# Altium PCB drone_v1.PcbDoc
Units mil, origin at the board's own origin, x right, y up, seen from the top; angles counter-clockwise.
Board outline 1968.5 x 1417.32 mil, 4 copper layers (Top Layer, GROUND, VCC, Bottom Layer); 89 components, 87 nets, 452 pads, 195 vias.
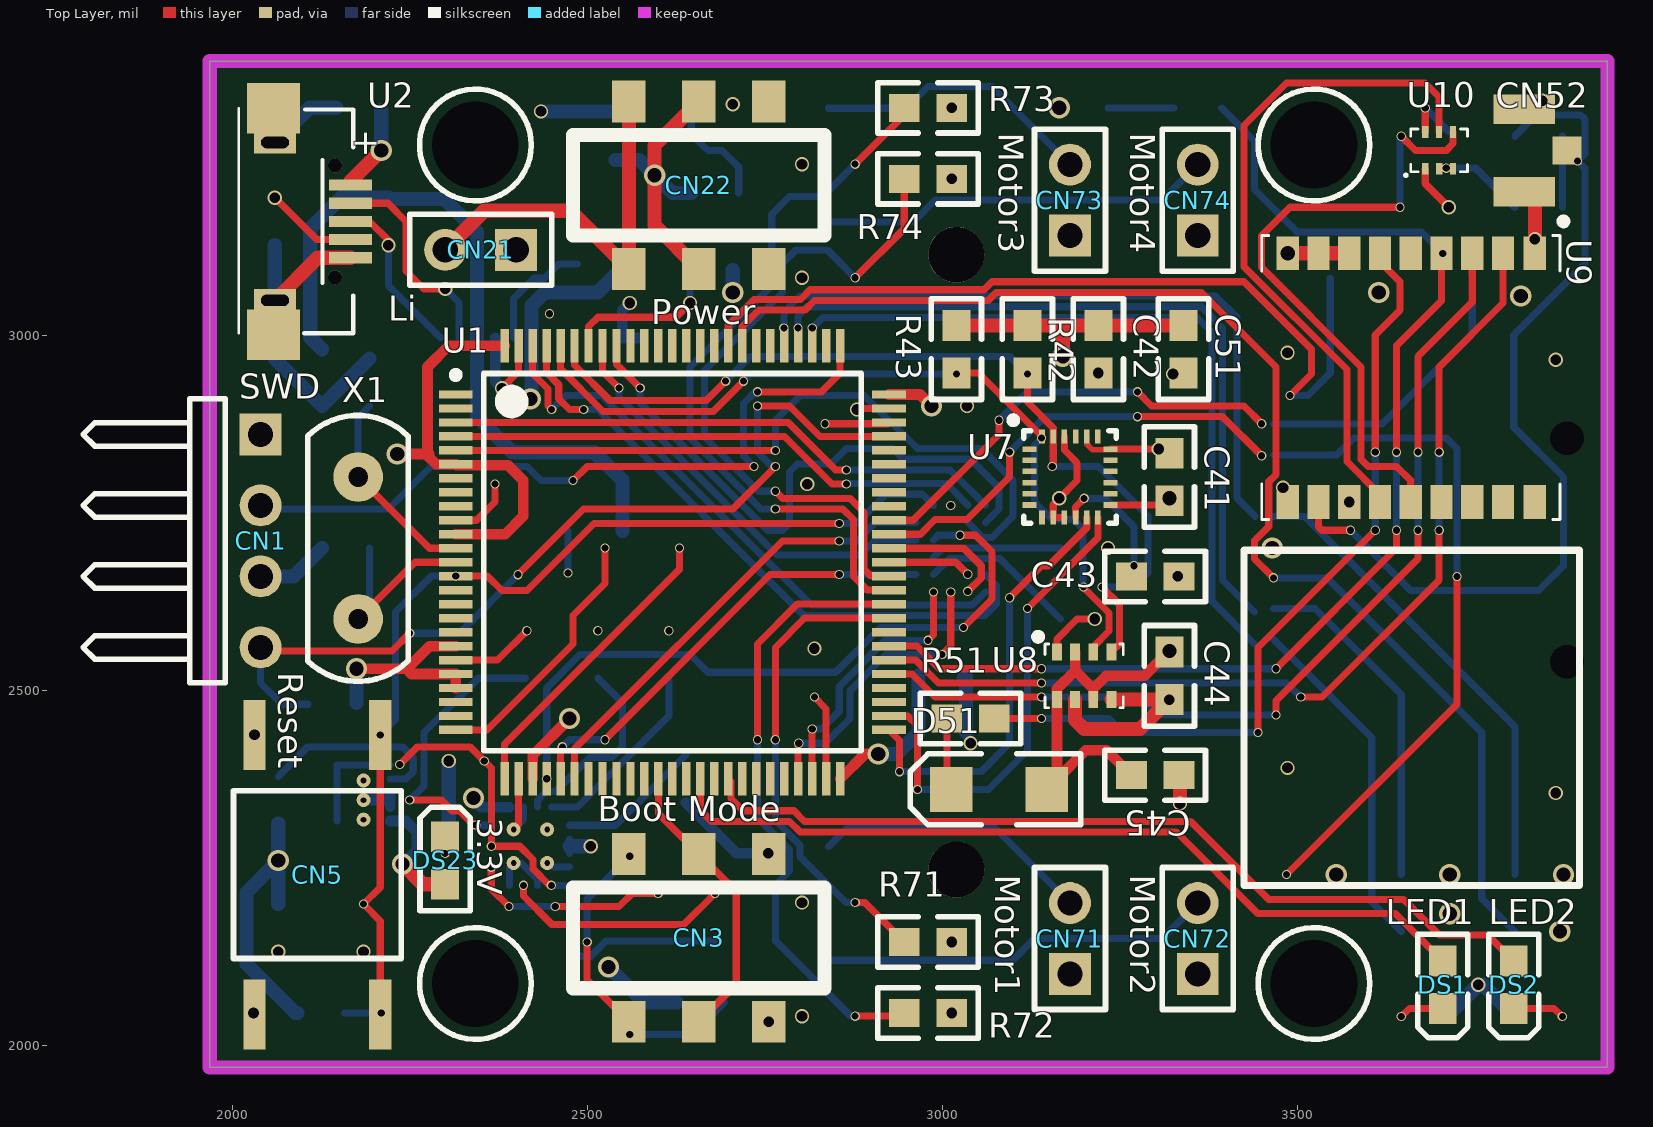
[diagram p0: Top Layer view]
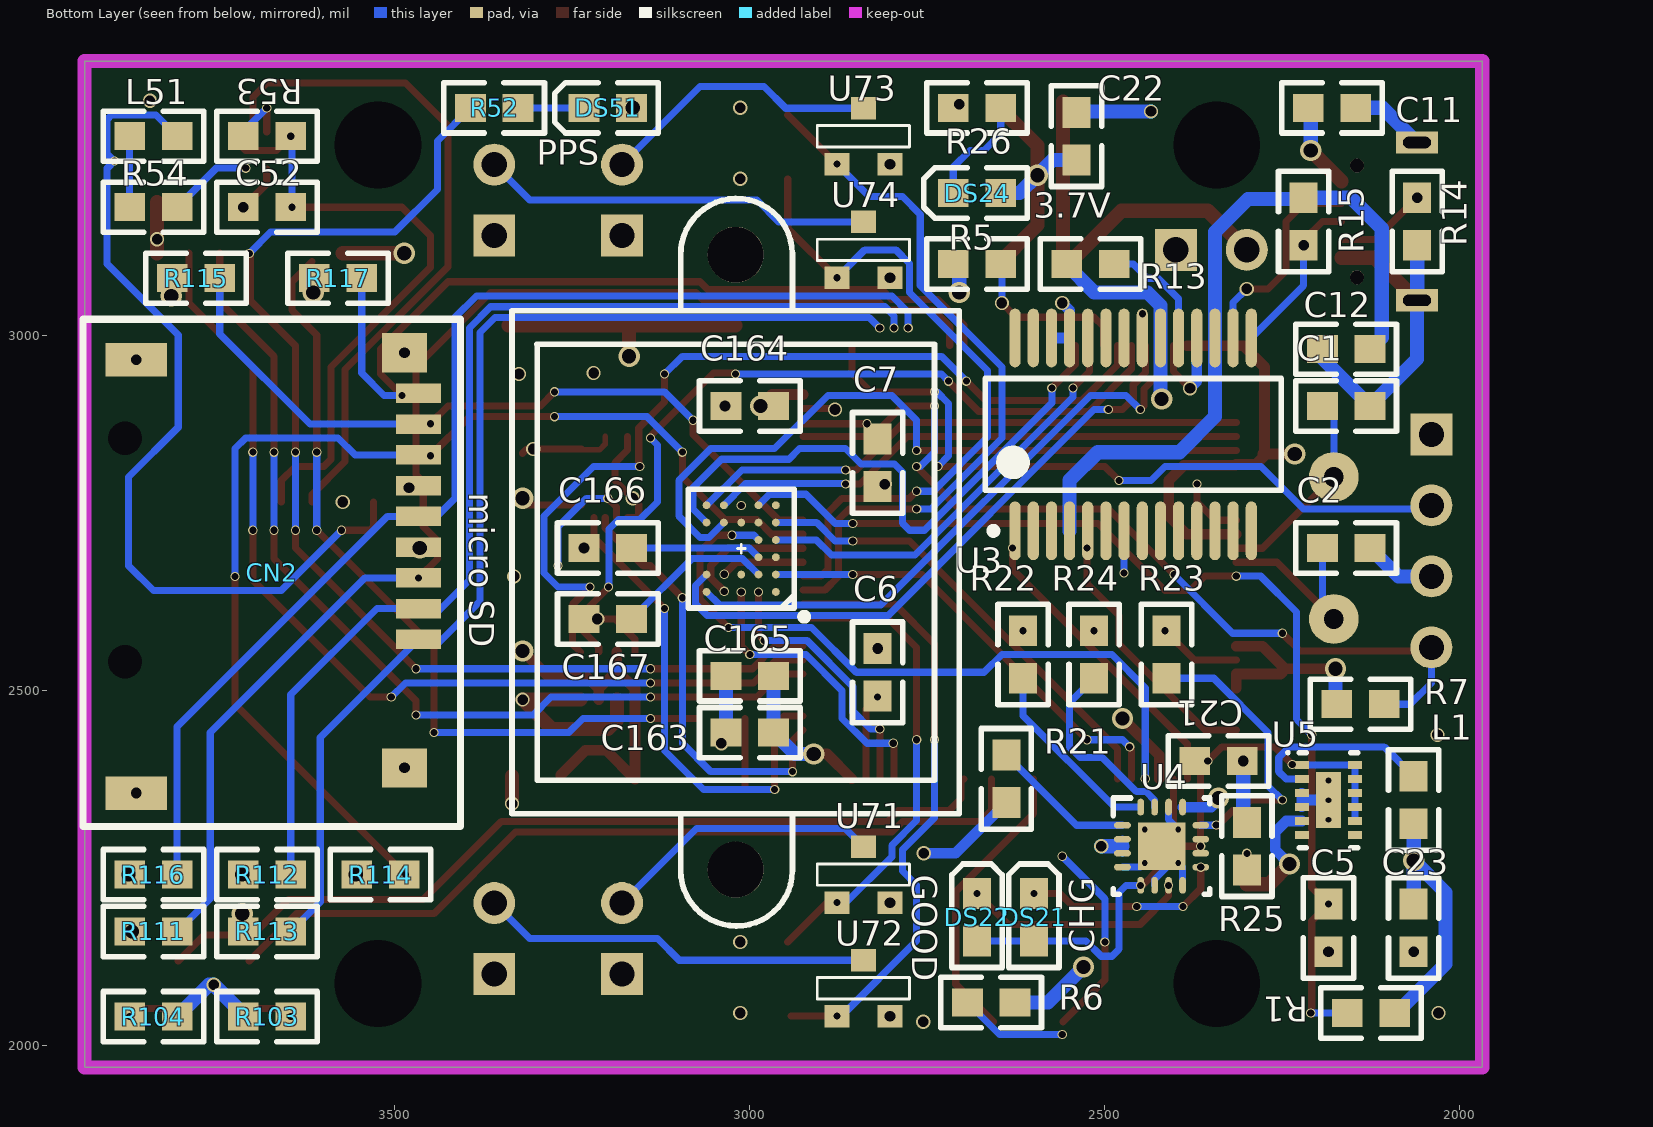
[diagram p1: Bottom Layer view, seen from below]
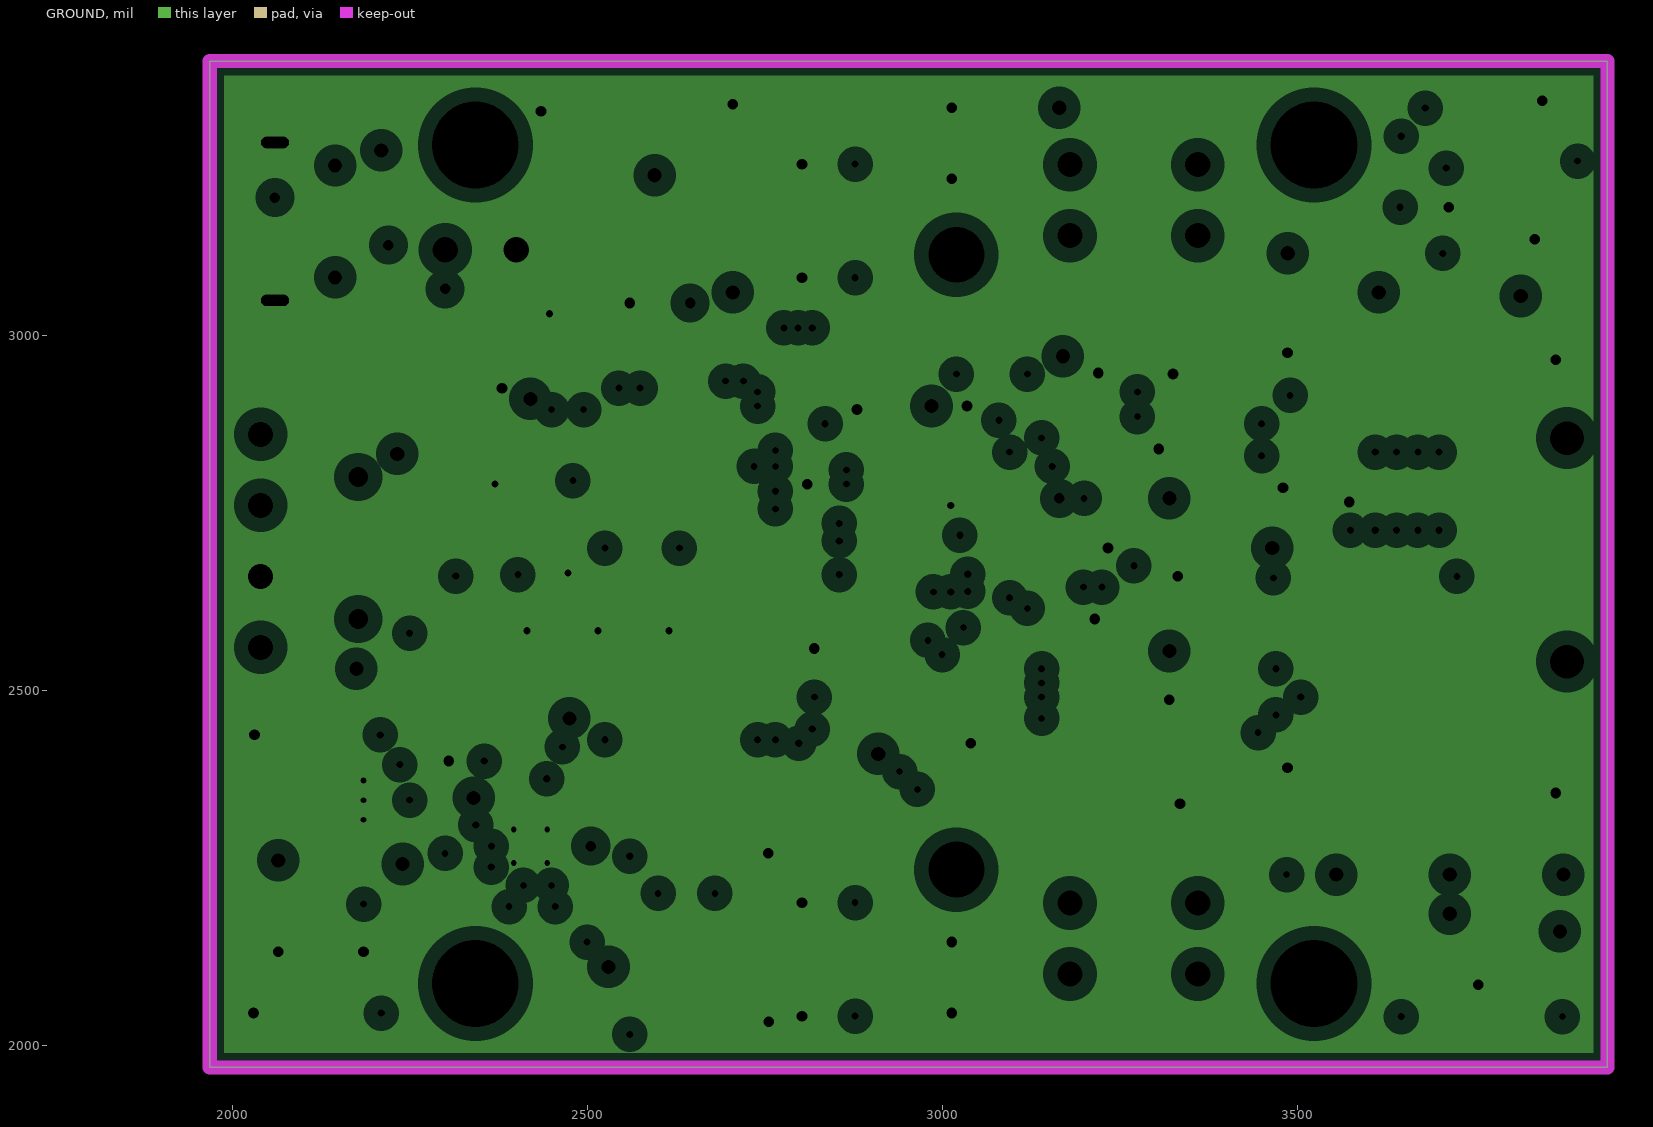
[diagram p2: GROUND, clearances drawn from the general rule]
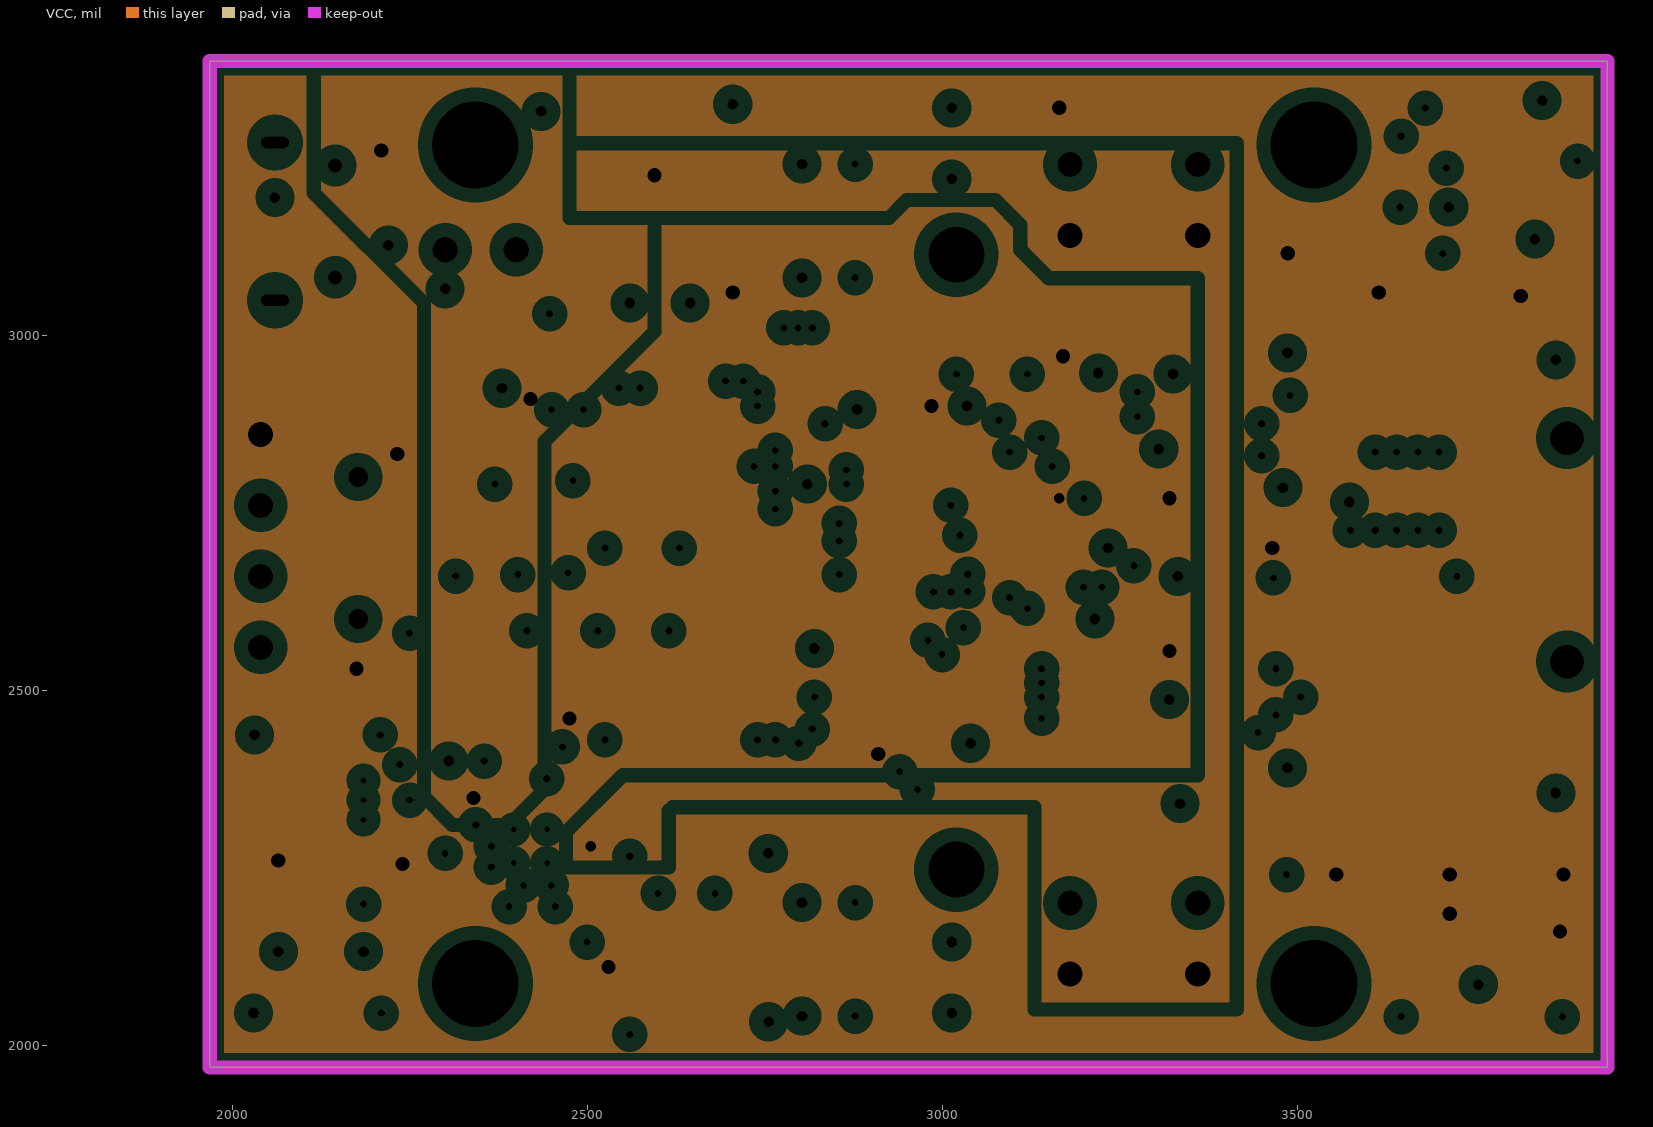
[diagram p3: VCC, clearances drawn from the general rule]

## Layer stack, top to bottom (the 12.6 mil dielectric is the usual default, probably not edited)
Top Layer: signal copper 1.4
Dielectric: core 12.6, FR-4, Dk 4.8
GROUND: plane copper 1.4, net GND
Dielectric: prepreg 12.6, FR-4, Dk 4.8
VCC: plane copper 1.4, net (Multiple Nets)
Dielectric: core 12.6, FR-4, Dk 4.8
Bottom Layer: signal copper 1.4

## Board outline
1968.5,3385.83 3937.01,3385.83 3937.01,1968.5 1968.5,1968.5 1968.5,3385.83

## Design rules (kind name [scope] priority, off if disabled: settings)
Clearance [All] p1: gap=5
ComponentClearance [All] p1: gap=-3937.01 collisioncheckmode=3 verticalgap=10 showdistances=FALSE
PlaneClearance [All] p1: clearance=20
PlaneConnect [All] p1: planeconnectstyle=Relief reliefexpansion=20 reliefentries=4 reliefconductorwidth=10 reliefairgap=10
PolygonConnect [All] p1: connectstyle=Relief reliefconductorwidth=10 reliefentries=4 polygonreliefangle="90 Angle"
RoutingVias [All] p1: holewidth=28 width=50 viastyle="Through Hole" minholewidth=28 minwidth=50 maxholewidth=28 maxwidth=50
SilkscreenOverComponentPads [All] p1: minsilkscreentomaskgap=10
SolderMaskExpansion [All] p1: expansion=4
Width [All] p1: maxlimit=40 minlimit=6 preferedwidth=6
24 further rules are at their usual default settings.

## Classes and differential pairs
component class camera: C163 C164 C165 C166 C167 U13
component class firmware: C11 C12 R13 R14 R15 U2 U3
component class gnss: C51 C52 CN52 D51 DS51 L51 R51 R52 R53 R54 U9 U10
component class mcu: C1 C2 C5 C6 C7 CN1 CN2 CN3 CN5 DS1 DS2 R1 R5 R6 R7 R103 R104 R111 R112 R113 R114 R115 R116 R117 U1 X1
component class motor: CN71 CN72 CN73 CN74 R71 R72 R73 R74 U71 U72 U73 U74
component class power: C21 C22 C23 CN21 CN22 DS21 DS22 DS23 DS24 L1 R21 R22 R23 R24 R25 R26 U4 U5
component class sensor: C41 C42 C43 C44 C45 R42 R43 U7 U8
net class DCMI_D[0..7]: DCMI_D0 DCMI_D1 DCMI_D2 DCMI_D3 DCMI_D4 DCMI_D5 DCMI_D6 DCMI_D7
net class MOTOR_D[0..3]: MOTOR0 MOTOR1 MOTOR2 MOTOR3 MOTOR_D0 MOTOR_D1 MOTOR_D2 MOTOR_D3

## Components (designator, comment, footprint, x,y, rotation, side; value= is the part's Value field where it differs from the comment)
C1 "Cap Semi" C1608-0603 2160,2900 r0 bottom
C2 "Cap Semi" C1608-0603 2160,2700 r0 bottom
C5 "Cap Semi" C1608-0603 2185,2165 r270 bottom
C6 "Cap Semi" C1608-0603 2820,2525 r270 bottom
C7 "Cap Semi" C1608-0603 2820,2820 r90 bottom
C11 "Cap Semi" C1608-0603 2180,3320 r180 bottom
C12 "Cap Semi" C1608-0603 2160,2980 r180 bottom
C21 "Cap Semi" C1608-0603 2340,2400 r0 bottom
C22 "Cap Semi" C1608-0603 2540,3280 r270 bottom
C23 "Cap Semi" C1608-0603 2065,2165 r270 bottom
C41 "Cap Semi" C1608-0603 3320,2800 r90 top
C42 "Cap Semi" C1608-0603 3220,2980 r270 top
C43 "Cap Semi" C1608-0603 3300,2660 r0 top
C44 "Cap Semi" C1608-0603 3320,2520 r90 top
C45 "Cap Semi" C1608-0603 3300,2380 r180 top
C51 "Cap Semi" C1608-0603 3340,2980 r270 top
C52 "Cap Semi" C1608-0603 3680,3180 r0 bottom
C163 "Cap Semi" C1608-0603 3000,2440 r0 bottom
C164 "Cap Semi" C1608-0603 3000,2900 r0 bottom
C165 "Cap Semi" C1608-0603 3000,2520 r0 bottom
C166 "Cap Semi" C1608-0603 3200,2700 r180 bottom
C167 "Cap Semi" C1608-0603 3200,2600 r180 bottom
CN1 "SWD" HDR1X4H 2040,2860 r270 top
CN2 "micro SD" MICRO_SD_PUSH 3880,2660 r270 bottom locked
CN3 "Boot Mode" SWITCH_6 2480,2080 r0 top
CN5 "Reset" Switch6X6 2120,2240 r270 top
CN21 "Li" HDR1X2 2400,3120 r180 top
CN22 "Power" SWITCH_6 2480,3140 r0 top
CN52 "IPEX" IPEX 3820,3260 r0 top
CN71 "Motor1" HDR1X2 3180,2100 r90 top
CN72 "Motor2" HDR1X2 3360,2100 r90 top
CN73 "Motor3" HDR1X2 3180,3140 r90 top
CN74 "Motor4" HDR1X2 3360,3140 r90 top
D51 "IN4148" D1206 3080,2360 r180 top
DS1 "LED1" LED0603_AB 3705,2085 r270 top
DS2 "LED2" LED0603_AB 3805,2085 r270 top
DS21 "CHG" LED0603_AB 2600,2180 r90 bottom
DS22 "GOOD" LED0603_AB 2680,2180 r90 bottom
DS23 "3.3V" LED0603_AB 2300,2260 r90 top
DS24 "3.7V" LED0603_AB 2680,3200 r0 bottom
DS51 "PPS" LED0603_AB 3200,3320 r0 bottom
L1 "Inductor" I1608-0603 2065,2345 r270 bottom
L51 "Inductor" I1608-0603 3840,3280 r0 bottom
R1 "Res Semi" R1608-0603 2125,2045 r0 bottom
R5 "Res Semi" R1608-0603 2680,3100 r180 bottom
R6 "Res Semi" R1608-0603 2660,2060 r0 bottom
R7 "Res Semi" R1608-0603 2140,2480 r180 bottom
R13 "Res Semi" R1608-0603 2520,3100 r180 bottom
R14 "Res Semi" R1608-0603 2060,3160 r270 bottom
R15 "Res Semi" R1608-0603 2220,3160 r270 bottom
R21 "Res Semi" R1608-0603 2638.78,2374.88 r270 bottom
R22 "Res Semi" R1608-0603 2615,2550 r270 bottom
R23 "Res Semi" R1608-0603 2413,2550 r270 bottom
R24 "Res Semi" R1608-0603 2515,2550 r270 bottom
R25 "Res Semi" R1608-0603 2300,2280 r270 bottom
R26 "Res Semi" R1608-0603 2680,3320 r180 bottom
R42 "Res Semi" R1608-0603 3120,2980 r270 top
R43 "Res Semi" R1608-0603 3020,2980 r270 top
R51 "Res Semi" R1608-0603 3040,2460 r180 top
R52 "Res Semi" R1608-0603 3360,3320 r180 bottom
R53 "Res Semi" R1608-0603 3680,3280 r0 bottom
R54 "Res Semi" R1608-0603 3840,3180 r0 bottom
R71 "Res Semi" R1608-0603 2980,2145 r180 top
R72 "Res Semi" R1608-0603 2980,2045 r180 top
R73 "Res Semi" R1608-0603 2980,3320 r180 top
R74 "Res Semi" R1608-0603 2980,3220 r180 top
R103 "Res Semi" R1608-0603 3680,2040 r0 bottom
R104 "Res Semi" R1608-0603 3840,2040 r180 bottom
R111 "Res Semi" R1608-0603 3840,2160 r180 bottom
R112 "Res Semi" R1608-0603 3680,2240 r180 bottom
R113 "Res Semi" R1608-0603 3680,2160 r180 bottom
R114 "Res Semi" R1608-0603 3520,2240 r0 bottom
R115 "Res Semi" R1608-0603 3780,3080 r0 bottom
R116 "Res Semi" R1608-0603 3840,2240 r180 bottom
R117 "Res Semi" R1608-0603 3580,3080 r180 bottom
U1 "STM32F407VGT6" LQFP100_V 2620,2680 r0 top locked
U2 "MICRO-USB" MICRO-USB 2080,3160 r270 top
U3 "IC_FT232RL" SSOP-28 2460,2860 r90 bottom locked
U4 "BQ24232RGTR" RGT0016C 2420,2280 r180 bottom
U5 "TPS62740DSST" DSS0012A 4085,345 r180 bottom
U7 "MPU9250" QFN24_3X3_MPU9250 3180,2800 r0 top locked
U8 "BMP280" LGA8_BMP280 3200,2520 r0 top
U9 "UBLOX_MAX7Q" UBLOX_MAX7Q 3660,2940 r90 top locked
U10 "SI1040X" SI1040X 3700,3260 r0 top
U71 "SOT23_SI2302" SOT23_SI2302 2840,2240 r180 bottom
U72 "SOT23_SI2302" SOT23_SI2302 2840,2080 r180 bottom
U73 "SOT23_SI2302" SOT23_SI2302 2840,3280 r180 bottom
U74 "SOT23_SI2302" SOT23_SI2302 2840,3120 r180 bottom
X1 "8MHz" XTAL-0.2 2020,2680 r90 top

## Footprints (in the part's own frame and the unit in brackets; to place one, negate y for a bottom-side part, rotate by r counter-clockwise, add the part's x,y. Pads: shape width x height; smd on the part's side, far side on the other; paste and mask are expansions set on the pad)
C1608-0603 [mm]
  rect 1.1x1 smd: 1(-0.85,0) 2(0.85,0)
  silkscreen extent -1.8,-0.9 1.8,0.9
D1206 [mm]
  rect 1.52x1.6 smd: 1(-1.71,0) 2(1.71,0)
  silkscreen extent -2.92,-1.27 3.17,1.27
DSS0012A [mm]
  rect 0.5x0.28 smd paste-0.14 mask+0.076: 1(47.31,52.05) 2(47.31,51.55) 3(47.31,51.05) 4(47.31,50.55) 5(47.31,50.05) 6(47.31,49.55) 7(49.21,49.55) 8(49.21,50.05) 9(49.21,50.55) 10(49.21,51.05) 11(49.21,51.55) 12(49.21,52.05)
  round 0.5 / inner round 1.524 / far side round 0.5 hole 0.2 mask+0.051: 13(48.26,50.8) 13(48.26,50.1) 13(48.26,51.5)
  rect 0.9x2 smd paste-0.45 mask+0.076: 13(48.26,50.8)
  silkscreen extent 46.76,49.1 49.31,52.55
HDR1X2 [mm] "Connector; Header; 2 Position"
  rect 1.5x1.5 hole 0.9: 1(0,0)
  round 1.5 hole 0.9: 2(2.54,0)
  silkscreen extent -1.27,-1.27 3.81,1.27
HDR1X4H [mm] "Connector; Header; 4 Position; Right Angle"
  rect 1.5x1.5 hole 0.9: 1(0,0)
  round 1.5 hole 0.9: 2(2.54,0) 3(5.08,0) 4(7.62,0)
  silkscreen extent -1.27,-6.35 8.89,-1.27
I1608-0603 [mm]
  rect 1.1x1 smd: 1(-0.85,0) 2(0.85,0)
  silkscreen extent -1.8,-0.9 1.8,0.9
IPEX [mm]
  rect 2.2x1.05 smd paste+0 mask+0.05: 1(0,1.475) 2(0,-1.475)
  rect 1.05x1 smd paste+0 mask+0.05: 3(1.525,0)
LED0603_AB [mm]
  rect 1.1x1 smd: 1(-0.85,0) 2(0.85,0)
  silkscreen extent -1.8,-0.9 1.91,0.9
LGA8_BMP280 [mm]
  rect 0.35x0.6 smd paste+0 mask+0.03: 1(-0.975,0.85) 2(-0.325,0.85) 3(0.325,0.85) 4(0.975,0.85) 5(0.975,-0.85) 6(0.325,-0.85) 7(-0.325,-0.85) 8(-0.975,-0.85)
  silkscreen extent -1.77,-1.14 1.4,1.52
LQFP100_V [mm] "Thin QFP, 100-Leads, Body 14x14mm, Pitch 0.5mm, ST Recommended"
  rect 1.2x0.3 smd: 1(-7.75,6) 2(-7.75,5.5) 3(-7.75,5) 4(-7.75,4.5) 5(-7.75,4) 6(-7.75,3.5) 7(-7.75,3) 8(-7.75,2.5) 9(-7.75,2) 10(-7.75,1.5) 11(-7.75,1) 12(-7.75,0.5) 13(-7.75,0) 14(-7.75,-0.5) 15(-7.75,-1) 16(-7.75,-1.5) 17(-7.75,-2) 18(-7.75,-2.5) 19(-7.75,-3) 20(-7.75,-3.5) 21(-7.75,-4) 22(-7.75,-4.5) 23(-7.75,-5) 24(-7.75,-5.5) 25(-7.75,-6) 51(7.75,-6) 52(7.75,-5.5) 53(7.75,-5) 54(7.75,-4.5) 55(7.75,-4) 56(7.75,-3.5) 57(7.75,-3) 58(7.75,-2.5) 59(7.75,-2) 60(7.75,-1.5) 61(7.75,-1) 62(7.75,-0.5) 63(7.75,0) 64(7.75,0.5) 65(7.75,1) 66(7.75,1.5) 67(7.75,2) 68(7.75,2.5) 69(7.75,3) 70(7.75,3.5) 71(7.75,4) 72(7.75,4.5) 73(7.75,5) 74(7.75,5.5) 75(7.75,6)
  rect 0.3x1.2 smd: 26(-6,-7.75) 27(-5.5,-7.75) 28(-5,-7.75) 29(-4.5,-7.75) 30(-4,-7.75) 31(-3.5,-7.75) 32(-3,-7.75) 33(-2.5,-7.75) 34(-2,-7.75) 35(-1.5,-7.75) 36(-1,-7.75) 37(-0.5,-7.75) 38(0,-7.75) 39(0.5,-7.75) 40(1,-7.75) 41(1.5,-7.75) 42(2,-7.75) 43(2.5,-7.75) 44(3,-7.75) 45(3.5,-7.75) 46(4,-7.75) 47(4.5,-7.75) 48(5,-7.75) 49(5.5,-7.75) 50(6,-7.75) 76(6,7.75) 77(5.5,7.75) 78(5,7.75) 79(4.5,7.75) 80(4,7.75) 81(3.5,7.75) 82(3,7.75) 83(2.5,7.75) 84(2,7.75) 85(1.5,7.75) 86(1,7.75) 87(0.5,7.75) 88(0,7.75) 89(-0.5,7.75) 90(-1,7.75) 91(-1.5,7.75) 92(-2,7.75) 93(-2.5,7.75) 94(-3,7.75) 95(-3.5,7.75) 96(-4,7.75) 97(-4.5,7.75) 98(-5,7.75) 99(-5.5,7.75) 100(-6,7.75)
  silkscreen extent -7.87,-6.75 6.75,6.82, body extent -7,-7 7,7, height 1.6
MICRO-USB [mm]
  rect 0.4x1.55 smd: 1(-1.3,2.2) 2(-0.65,2.2) 3(0,2.2) 4(0.65,2.2) 5(1.3,2.2)
  rect 1.8x1.9 smd: 6(-4.05,-0.55) 6(4.05,-0.55)
  rect 0.8x1.5 hole 0.4 slot 1 at 90 deg: 6(-2.825,-0.5) 6(2.825,-0.5)
  round 0.5 hole 0.5 unplated: ""(-2,1.65) ""(2,1.65)
  silkscreen extent -4.05,-1.8 4,2.3
MICRO_SD_PUSH [mm]
  rect 0.7x1.6 smd: 1(2.25,10.5) 2(1.15,10.5) 3(0.05,10.5) 4(-1.05,10.5) 5(-2.15,10.5) 6(-3.25,10.5) 7(-4.35,10.5) 8(-5.45,10.5) 9(-6.55,10.5)
  rect 1.4x1.6 smd: 10(-8,10) 10(6.85,10)
  rect 1.2x2.2 smd: 10(-7.75,0.4) 10(7.75,0.4)
  round 1 hole 1.2: ""(-4.95,0) ""(3.05,0)
  silkscreen extent -9.2,-1.5 8.95,12
QFN24_3X3_MPU9250 [mm]
  rect 0.5x0.2 smd paste+0 mask+0.03: 1(-1.45,1) 2(-1.45,0.6) 3(-1.45,0.2) 4(-1.45,-0.2) 5(-1.45,-0.6) 6(-1.45,-1) 13(1.45,-1) 14(1.45,-0.6) 15(1.45,-0.2) 16(1.45,0.2) 17(1.45,0.6) 18(1.45,1)
  rect 0.2x0.5 smd paste+0 mask+0.03: 7(-1,-1.45) 8(-0.6,-1.45) 9(-0.2,-1.45) 10(0.2,-1.45) 11(0.6,-1.45) 12(1,-1.45) 19(1,1.45) 20(0.6,1.45) 21(0.2,1.45) 22(-0.2,1.45) 23(-0.6,1.45) 24(-1,1.45)
  silkscreen extent -2.15,-1.65 1.65,2.16
R1608-0603 [mm]
  rect 1.1x1 smd: 1(-0.85,0) 2(0.85,0)
  silkscreen extent -1.8,-0.9 1.8,0.9
RGT0016C [mm]
  oval 0.6x0.24 smd paste-0.102 mask+0.051: 1(-1.4,0.75) 2(-1.4,0.25) 3(-1.4,-0.25) 4(-1.4,-0.75) 9(1.4,-0.75) 10(1.4,-0.25) 11(1.4,0.25) 12(1.4,0.75)
  oval 0.24x0.6 smd paste-0.102 mask+0.051: 5(-0.75,-1.4) 6(-0.25,-1.4) 7(0.25,-1.4) 8(0.75,-1.4) 13(0.75,1.4) 14(0.25,1.4) 15(-0.25,1.4) 16(-0.75,1.4)
  round 0.5 / inner round 1.524 / far side round 0.5 hole 0.203 mask+0.051: 17(-0.6,-0.6) 17(-0.6,0.6) 17(0.6,-0.6) 17(0.6,0.6)
  rect 1.7x1.7 smd paste-0.837 mask+0.051: 17(0,0)
  silkscreen extent -1.72,-1.73 1.72,1.73
SI1040X [mm]
  rect 0.22x0.42 smd paste+0 mask+0.05: 1(-0.5,-0.66) 2(0,-0.66) 3(0.5,-0.66) 4(0.5,0.66) 5(-0.008,0.66) 6(-0.5,0.66)
  silkscreen extent -1.24,-0.94 1.02,0.76
SOT23_SI2302 [mm]
  rect 0.9x0.8 smd: 1(-0.95,-1) 2(0.95,-1) 3(0,1)
  silkscreen extent -1.65,-0.38 1.65,0.38
SSOP-28 [mm] "28-Pin SSOP 0.65 mm Pitch"
  oval 2.1x0.4 smd: 1(-3.45,4.225) 2(-3.45,3.575) 3(-3.45,2.925) 4(-3.45,2.275) 5(-3.45,1.625) 6(-3.45,0.975) 7(-3.45,0.325) 8(-3.45,-0.325) 9(-3.45,-0.975) 10(-3.45,-1.625) 11(-3.45,-2.275) 12(-3.45,-2.925) 13(-3.45,-3.575) 14(-3.45,-4.225) 15(3.45,-4.225) 16(3.45,-3.575) 17(3.45,-2.925) 18(3.45,-2.275) 19(3.45,-1.625) 20(3.45,-0.975) 21(3.45,-0.325) 22(3.45,0.325) 23(3.45,0.975) 24(3.45,1.625) 25(3.45,2.275) 26(3.45,2.925) 27(3.45,3.575) 28(3.45,4.225)
  silkscreen extent -3.57,-5.3 2,5.3, body extent -2.7,-5.3 2.7,5.3, height 2
Switch6X6 [mm]
  rect 2.5x0.8 smd: 1(-5,2.25) 2(5,2.25) 3(-5,-2.25) 4(5,-2.25)
  silkscreen extent -3,-3 3,3
SWITCH_6 [mm]
  rect 1.2x1.5 smd: 1(2,4.8) 2(4.5,4.8) 3(7,4.8) 4(2,-1.2) 5(4.5,-1.2) 6(7,-1.2)
  silkscreen extent 0,0 9,3.6
UBLOX_MAX7Q [mm]
  rect 1.2x0.8 smd paste+0 mask+0.05: 1(4.45,-4.44) 2(4.45,-3.3) 3(4.45,-2.2) 4(4.45,-1.1) 5(4.45,0) 6(4.45,1.1) 7(4.45,2.2) 8(4.45,3.3) 9(4.45,4.4) 10(-4.45,4.4) 11(-4.45,3.3) 12(-4.45,2.2) 13(-4.45,1.1) 14(-4.45,0) 15(-4.45,-1.1) 16(-4.45,-2.2) 17(-4.45,-3.3) 18(-4.45,-4.44)
  silkscreen extent -5.08,-5.59 5.71,5.33
XTAL-0.2 [mil]
  round 70 hole 28: 1(-79.92,-157.48) 2(120.08,-157.48)
  silkscreen extent -168,-228 207,-86

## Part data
C1 C2 C5 C6 C7 C11 C12 C21 C22 C23 C41 C42 C43 C44 C45 C51 C52 C163 C164 C165 C166 C167: "Capacitor (Semiconductor SIM Model)"
CN1: library part "Header 4H", "Header, 4-Pin, Right Angle"
CN2: library part MICRO_SD_PUSH
CN3 CN22: library part SWITCH_6
CN5: library part Switch6X6, "Switch"
CN21 CN71 CN72 CN73 CN74: library part "Header 2", "Header, 2-Pin"
D51: library part Diode, "Default Diode"
DS1 DS2 DS21 DS22 DS23 DS24 DS51: library part LED3, "Typical BLUE SiC LED"
R1 R5 R6 R7 R13 R14 R15 R21 R22 R23 R24 R25 R26 R42 R43 R51 R52 R53 R54 R71 R72 R73 R74 R103 R104 R111 R112 R113 R114 R115 R116 R117: "Semiconductor Resistor"
U3: "FT232R USB UART"
U4 U5: "Imported"
U7: library part QFN24_3X3_MPU9250
U8: library part LGA8_BMP280
X1: library part XTAL, "Crystal Oscillator"

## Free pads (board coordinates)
  round 118.11 hole 122.05: 0(2342.52,2086.61) 0(2342.52,3267.72) 0(3523.62,2086.61) 0(3523.62,3267.72)
  round 78.74 hole 78.74: 1(3020,3113.07) 2(3020,2246.93)
  round 11.02 smd far side: A1(2963.31,2638.2) A2(2987.72,2638.2) A3(3012.13,2638.2) A4(3036.54,2638.2) A5(3060.95,2638.2) B1(2963.31,2662.61) B2(2987.72,2662.61) B3(3012.13,2662.61) B4(3036.54,2662.61) B5(3060.95,2662.61) C1(2963.31,2687.02) C2(2987.72,2687.02) D1(2963.31,2711.43) D2(2987.72,2711.43) E1(2963.31,2735.83) E2(2987.72,2735.83) E3(3012.13,2735.83) E4(3036.54,2735.83) E5(3060.95,2735.83) F1(2963.31,2760.24) F2(2987.72,2760.24) F3(3012.13,2760.24) F4(3036.54,2760.24) F5(3060.95,2760.24)

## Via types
v1: diameter 13, hole 10, Top Layer to Bottom Layer, 121 vias
v2: diameter 20, hole 15, Top Layer to Bottom Layer, 48 vias
v3: diameter 30, hole 20, Top Layer to Bottom Layer, 26 vias

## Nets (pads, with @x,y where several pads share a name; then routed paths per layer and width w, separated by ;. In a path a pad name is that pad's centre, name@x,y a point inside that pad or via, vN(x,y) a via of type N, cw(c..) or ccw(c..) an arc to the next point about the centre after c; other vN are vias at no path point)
3.3V: C23.1 C41.1 C42.1 C44.2 C45.2 C51.1 C163.1 C164.1 C165.1 CN1.1 CN2.4 D51.1 DS23.1 DS51.1 L1.2 R1.1 R5.1 R6.1 R7.1 R42.1 R43.1 R111.1 R112.1 R113.1 R114.2 R115.2 R116.1 R117.1 U1.6 U1.11 U1.19 U1.21 U1.22 U1.28 U1.50 U1.75 U1.100 U5.5 U7.8 U7.9 U7.13 U7.22 U8.2 U8.6 U8.8 U9.7 U9.8 U9.9 | length 3164.2
  Top Layer w10: U7.9 U7.8 3156.38,2761.38 v2(3165,2770) 3190,2795 3190,2820 3172.13,2837.87 U7.22 ; U7.13 C41.1@3314.09,2760.63
  Top Layer w15: v3(2175,2530) 2245,2530 2252.48,2522.52 U1.21 U1.22 ; v3(2232.5,2832.5) 2277.5,2832.5 2275,2830 ; 2246.22,2530 2278.11,2561.89 U1.19 ; U1.11 2384.37,2719.37 2410,2745 2410,2795 2388.48,2816.52 2316.16,2816.52 U1.6 2287.2,2817.8 2275,2830 ; U1.100 2305.12,2985.12 2275,2955 2275,2830 ; U1.28 2423.15,2408.15 v3(2475,2460) ; U1.50 2891.34,2410 v3(2910,2410) ; U1.75 2968.78,2916.22 v3(2985,2900) ; U8.2 3187.2,2527.2 ; U8.6 3212.8,2501.61 ; C45.2 3231.54,2415 3202.32,2415 3161.61,2374.29 U8.8 3161.61,2501.61 3187.2,2527.2 ; v3(3320,2555) 3285,2520 3231.18,2520 3212.8,2501.61 ; 3187.2,2527.2 3212.8,2501.61
  Top Layer w20: v3(2240,2255) 2268.46,2226.54 DS23.1 ; R43.1 R42.1 3170,3013.46 ; v3(3170,2970) 3170,3013.46 ; C51.1 C42.1 3170,3013.46 ; v3(3486.77,3115.2) U9.8 U9.7
  Bottom Layer w15: U5.5 2244.53,2315.47 2260,2300 2260,2275 v3(2240,2255)
  Bottom Layer w20: C23.1 v3(2065,2260) ; L1.2 v3(2065,2260) ; R1.1 2088.98,2045 2020,2113.98 2020,2215 v3(2065,2260) ; R7.1@2175,2481.54 v3(2175,2530) ; v3(2530,2110) 2580,2060 R6.1 ; v3(2705,3060) R5.1@2705,3091.54 ; v3(2910,2410) 2936.54,2410 C163.1 C165.1
  other v3: 3870,2160 3715,2185 3555,2240 3715,2240 3875,2240 3465,2700 3320,2770 3815,3055 3615,3060 3165,3320
3.3V_FT232: C12.2 R15.1 U3.4 U3.17 | length 1020.3
  Bottom Layer w20: C12.2 2110,2996.54 2110,3150 2153.46,3193.46 R15.1 ; R15.1@2221.77,3191.69 2298.31,3191.69 2344.84,3145.16 U3.17 2344.84,2885.16 2395,2835 2510,2835 2549.57,2795.43 U3.4
3.7V_LI: C22.2 CN22.2 CN22.5 CN71.1 CN72.1 CN73.1 CN74.1 DS24.1 U4.2 U4.3 | length 463.1
  Top Layer w20: CN22.5 2595,3154.92 v3(2595,3225) 2595,3266.81 CN22.2
  Bottom Layer w10: U4.3 2475.12,2280 U4.2
  Bottom Layer w20: 2475.12,2280 v2(2505,2280) ; C22.2 2573.46,3246.54 v3(2595,3225) 2620,3200 DS24.1
4.4V_BQOUT: C21.2 DS21.1 DS22.1 U4.5 U4.10 U4.11 U5.1 U5.8 U5.9 U5.10 U5.11 U5.12 | length 857.9
  Top Layer w10: v1(2236,2395) 2261,2420 2335,2420 v1(2355,2400) 2365,2390 v1(2365,2280) 2405,2280 2423.78,2261.22 2423.78,2248.16 2447.06,2224.88 v1(2449.53,2224.88)
  Bottom Layer w10: U5.8 U5.9 U5.10 U5.11 U5.12 2147.76,2394.37 U5.1@2222.24,2394.37 ; v1(2449.53,2224.88) 2470.12,2224.88 2480,2215 2480,2135 2490,2125 2505,2125 2526.54,2146.54 DS21.1 DS22.1
5V_USB: C11.1 R13.1 U2.1 U3.20 U4.13 | length 461
  Top Layer w20: U2.1@2166.61,3216.61 v3(2210,3260)
  Bottom Layer w15: v3@2340,2345 2349.88,2335.12 U4.13@2390.43,2335.12
  Bottom Layer w20: v3(2210,3260) C11.1@2210,3316.54 ; v3@2421.61,2910 2421.61,2985.83 2421.61,3041.61 2440,3060 2515,3060 2553.46,3098.46 R13.1
  other v3: 2340,2348 2420,2910
BOOT1: CN3.2 CN3.5 U1.37 | length 409.4
  Top Layer w10: U1.37 2600.32,2325.83 CN3.2 2710,2216.14 2710,2085.59 CN3.5
DCMI_D0: pad.B4 U1.63 | length 117.9
  Top Layer w10: U1.63 3019,2680 v1(3036,2663)
DCMI_D1: pad.A4 U1.64 | length 184
  Top Layer w10: U1.64 3030.32,2699.68 3055,2675 3055,2658 v1(3036,2639)
DCMI_D2: pad.B5 U1.97 | length 879.4
  Top Layer w10: U1.97 2442.83,2947.17 2460,2930 2460,2910 2475,2895 v1(2495,2895)
  Bottom Layer w10: v1(2495,2895) 2515,2895 2805,2605 3060,2605 3076.46,2621.46 3076.46,2647.09 pad.B5
DCMI_D3: pad.A5 U1.98 | length 850.2
  Top Layer w10: U1.98 2423.15,2945.64 2445,2923.79 2445,2900 v1(2450,2895)
  Bottom Layer w10: v1(2450,2895) 2470,2915 2520,2915 2815,2620 3042.75,2620 pad.A5
DCMI_D4: pad.F5 U1.3 | length 794.4
  Top Layer w10: U1.3 2783.15,2876.85 2850,2810 v1(2865,2810)
  Bottom Layer w10: v1(2865,2810) 3011.19,2810 pad.F5
DCMI_D5: pad.E5 U1.92 | length 844
  Top Layer w10: U1.92 2541.26,2958.74 v1(2574.65,2925.35)
  Bottom Layer w10: v1(2574.65,2925.35) 2574.65,2904.14 2753.79,2725 2775,2725 2785,2735 2785,2807.02 2796.17,2818.19 2843.19,2818.19 2865,2840 2930,2840 2945,2825 3040,2825 3080,2785 3080,2754.89 pad.E5
DCMI_D6: pad.F4 U1.4 | length 762.1
  Top Layer w10: U1.4 2777.83,2857.17 2845,2790 v1(2865,2790)
  Bottom Layer w10: v1@2865,2790.76 3006.02,2790.76 pad.F4
DCMI_D7: pad.E4 U1.5 | length 1026.4
  Top Layer w10: U1.5 v1(2765,2837.48)
  Bottom Layer w10: v1(2765,2837.48) 2765,2880 2800,2915 2890,2915 2965,2840 3055,2840 3100,2795 3100,2745 3070,2715 3057.37,2715 pad.E4
GND: C1.1 C2.1 C5.2 C6.1 C7.1 C11.2 C12.1 C21.1 C22.1 C23.2 C41.2 C42.2 C43.2 C44.1 C45.1 C51.2 C52.2 C163.2 C164.2 C165.2 C166.1 C167.1 CN1.3 CN2.6 CN2.10 CN3.3 CN3.6 CN5.3 CN5.4 CN21.1 CN52.1 CN52.2 pad.F3 R14.2 R21.2 R22.1 R23.1 R24.1 R25.1 R26.1 R71.1 R72.1 R73.1 R74.1 R103.2 R104.2 U1.10 U1.20 U1.27 U1.74 U1.99 U2.5 U2.6 U3.7 U3.18 U3.21 U3.25 U3.26 U4.4 U4.6 U4.8 U4.14 U4.17 U5.3 U5.4 U5.13 U7.18 U7.20 U8.1 U8.5 U8.7 U9.1 U9.10 U9.12 U10.1 U71.2 U72.2 U73.2 U74.2 | length 2706.5
  Top Layer w8: U7.20 3203.62,2846.33 3211.71,2838.24 3235.96,2838.24 U7.18
  Top Layer w10: U1.20 2373.74,2542.2 v1(2415,2583.46) ; U1.10 2344.06,2739.06 2370,2765 v1(2370,2790) ; v2(2380,2925) 2403.46,2948.46 U1.99 ; U4.17@2396.38,2303.62 2403.46,2310.71 U1.27 ; v2@2881.54,2896.54 U1.74 ; U8.1 3161.61,2571.61 3190,2600 v2(3215,2600) ; U7.18 3314.09,2839.37 C41.2 ; U10.1 3680.32,3213.15 v2(3713.46,3180)
  Top Layer w20: U2.6@2060.32,3048.78 2120.36,3108.82 U2.5 ; U8.7 3187.2,2457.8 3200,2445 3278.46,2445 v2(3320,2486.54) U8.5 ; v2(3335,2340) C45.1@3335,2378.46 ; U9.1 CN52.2@3834.8,3187.13
  Bottom Layer w10: U4.8 2390.47,2250.47 U4.17@2396.38,2256.38 ; U4.17@2396.38,2303.62 2410.16,2317.4 U4.14 ; U4.17@2406.57,2256.38 2429.84,2233.11 U4.6 ; U4.17@2443.62,2256.38 2449.53,2250.47 U4.4 ; v1@2472.8,2667.8 U3.7
  Bottom Layer w15: U5.13@2185,2345 2222.4,2345 ; U5.4@2222.4,2335.47 2222.4,2345 ; U5.3 2222.4,2345 ; U3.18 2370.43,2934.57 v2(2380,2925) ; v2(2560,3045) 2549.57,3034.57 U3.25 U3.26 ; R21.2 2710.2,2270 v2(2755,2270)
  Bottom Layer w20: CN1.3 2086.54,2660 C2.1 ; U2.6@2060,3049.09 R14.2 ; U2.6@2060.32,3048.78 2060.32,2966.22 C1.1 C12.1@2193.46,2966.93 ; U2.6@2060.32,3271.22 2109.09,3320 C11.2 ; R25.1@2305,2318.46 v2(2305,2400) ; v2(2435,3315) C22.1@2538.46,3315 ; C165.2@3030,2516.54 C165.2 C163.2 ; R103.2 3713.46,2043.46 v2(3755,2085) 3761.54,2085 R104.2
  other v1: 2515,2583.46 2615,2583.46 2473,2665 3012,2760 2447,3030
  other v2: 2755.59,2032.76 2802.6,2040.63 2030,2045 3013.46,2045 2065,2131.54 2185,2131.54 3013.46,2145 2802.6,2200.63 3864.25,2354.88 3486.3,2390.32 3040,2425 2031.42,2436.85 2820,2558.46 3332,2660 3233.46,2700 3573.39,2764.8 3480,2785 2810,2790 3305,2839.37 2880,2895 3035,2900 3325,2945 3220,2946.54 3864.25,2965.12 3486.3,2974.96 2802.6,3080.63 3834.8,3135 3013.46,3220 2802.6,3240.63 3013.46,3320 2705,3325 3845,3330
MOTOR_D0: R71.2 U1.59 U71.1 | length 682.9
  Top Layer w10: v1(2765,2430) 2765,2560 2806.26,2601.26 U1.59 ; v1(2877.4,2200.63) 2890.91,2200.63 R71.2
  Bottom Layer w10: v1(2765,2430) 2765,2316.21 2800,2281.21 2800,2265 2864.37,2200.63 v1(2877.4,2200.63)
MOTOR_D1: R72.2 U1.60 U72.1 | length 868.3
  Top Layer w10: v1(2740,2430) 2740,2565 2795.94,2620.94 U1.60 ; v1(2877.4,2040.63) R72.2@2942.17,2040.63
  Bottom Layer w10: v1(2740,2430) 2740,2320 2785,2275 2785,2245 2765,2225 2765,2146.76 U72.1@2871.13,2040.63
MOTOR_D2: R73.2 U1.61 U73.1 | length 1022.8
  Top Layer w10: v1(2765,2755) 2860,2755 2875,2740 2875,2660 2894.37,2640.63 U1.61 ; v1(2877.4,3240.63) R73.2@2946.54,3309.76
  Bottom Layer w10: v1(2765,2755) 2745,2755 2645,2855 2645,2955 2759.88,3069.88 2759.88,3169.88 2785,3195 2831.77,3195 v1(2877.4,3240.63)
MOTOR_D3: R74.2 U1.62 U74.1 | length 972.8
  Top Layer w10: v1(2765,2780) 2775,2770 2870,2770 2890,2750 2890,2670 2899.68,2660.32 U1.62 ; v1(2877.4,3080.63) 2946.54,3149.76 R74.2
  Bottom Layer w10: v1(2765,2780) 2741.21,2780 2665,2856.21 2665,2950 2774.88,3059.88 2774.88,3100.52 2794.36,3120 2838.03,3120 v1(2877.4,3080.63)
NetC1_2: C1.2 U1.12 X1.2 | length 285.5
  Top Layer w10: X1.2 2277.87,2699.68 U1.12
  Bottom Layer w10: X1.2 2177.48,2884.02 C1.2
NetC2_2: C2.2 U1.13 X1.1 | length 277
  Top Layer w10: X1.1 2257.4,2680 U1.13
  Bottom Layer w10: X1.1 2193.46,2616.06 C2.2
NetC6_2: C6.2 U1.49 | length 122
  Top Layer w10: v1(2820,2490) 2836.54,2473.46 U1.49
NetC7_2: C7.2 U1.73 | length 88.3
  Top Layer w10: v1(2835,2875) U1.73@2923.27,2875
NetC43_1: C43.1 U7.10 | length 173.7
  Top Layer w10: U7.10 3187.87,2757.87 v1(3200,2770)
  Bottom Layer w10: v1(3200,2770) 3230,2770 3270,2730 v1(3270,2675)
NetC52_1: C52.1 R53.1 U9.14 U10.4 | length 897.4
  Top Layer w10: v1(3645,3180) 3490,3180 3450,3140 3450,3095 3590,2955 3590,2825 3600,2815 3640,2815 3660,2795 U9.14 ; v1(3646.54,3280) 3666.54,3260 3710,3260 3719.68,3269.68 U10.4
  Bottom Layer w10: v1(3645,3180) R53.1@3645,3278.46
NetC166_2: C166.2 pad.C2 | length 184.2
  Bottom Layer w10: pad.C2 3000.7,2700 C166.2
NetC167_2: C167.2 pad.B2 | length 223.3
  Bottom Layer w10: pad.B2 3010.11,2685 3081.54,2685 C167.2
NetCN3_1: CN3.1 CN3.4 R6.2 | length 434.5
  Top Layer w10: v1(2500,2145) 2500,2091.5 CN3.4
  Bottom Layer w10: v1(2500,2145) 2500,2205.95 v1(2560,2265.95) ; v1(2560,2015) 2648.46,2015 R6.2
NetCN21_2: CN21.2 CN22.1 CN22.4 | length 551.8
  Top Layer w20: CN21.2 2355,3175 2476.5,3175 CN22.4 CN22.1
NetCN52_3: CN52.3 L51.1 U9.11 | length 1252.8
  Top Layer w10: U9.11 3530.08,2729.92 3535,2725 v1(3575,2725)
  Bottom Layer w10: v1(3575,2725) 3660,2640 3840,2640 3875,2675 3875,2800 3805,2870 3805,3000 3905.12,3100.12 3905.12,3234.88 v1(3895,3245) 3905.12,3255.12 3905.12,3303.83 3898.95,3310 3836.54,3310 L51.1
NetCN71_2: CN71.2 U71.3 | length 394.1
  Bottom Layer w10: U71.3 2865.63,2305 3075,2305 CN71.2
NetCN72_2: CN72.2 U72.3 | length 553.4
  Bottom Layer w10: U72.3 3099.37,2119.37 3130,2150 3310,2150 CN72.2
NetCN73_2: CN73.2 U73.3 | length 398.3
  Bottom Layer w10: U73.3 2949.37,3319.37 2980,3350 3070,3350 CN73.2
NetCN74_2: CN74.2 U74.3 | length 553.4
  Bottom Layer w10: U74.3 2959.37,3159.37 2990,3190 3310,3190 CN74.2
NetD51_2: D51.2 R51.2 | length 93.9
  Top Layer w10: D51.2@3006.54,2366.14 R51.2
NetDS1_1: DS1.1 U1.40 | length 1177.8
  Top Layer w10: U1.40 2659.37,2330.63 2675,2315 2785,2315 2800,2300 3330,2300 3445,2185 3638.46,2185 DS1.1
NetDS1_2: DS1.2 R103.1 | length 63.2
  Top Layer w10: v1(3646.54,2040) 3658.07,2051.54 DS1.2
NetDS2_1: DS2.1 U1.42 | length 1226.5
  Top Layer w10: U1.42 2702.52,2371.1 2702.52,2347.12 2719.64,2330 2791.21,2330 2806.21,2315 3350,2315 3460,2205 3650,2205 3700,2155 3768.46,2155 DS2.1
NetDS2_2: DS2.2 R104.1 | length 73.2
  Top Layer w10: DS2.2 3861.93,2051.54 v1(3873.46,2040)
NetDS21_2: DS21.2 U4.9 | length 283.5
  Top Layer w10: v1(2364.88,2250.47) 2364.88,2220.12 v1(2390,2195) ; v1(2455,2195) 2545,2195 2563.46,2213.46 v1(2600,2213.46)
  Bottom Layer w10: v1(2390,2195) v1(2455,2195)
NetDS22_2: DS22.2 U4.7 | length 319.4
  Top Layer w10: v1(2410.16,2224.88) 2410.16,2209.84 2450,2170 2636.54,2170 v1(2680,2213.46)
NetDS23_2: DS23.2 R25.2
  other v1: 2300,2270
NetDS24_2: DS24.2 R26.2 | length 159.4
  Bottom Layer w10: R26.2 2646.54,3283.46 2670,3260 2690,3260 2713.46,3236.54 DS24.2
NetDS51_2: DS51.2 R52.2 | length 93.1
  Bottom Layer w10: DS51.2 R52.2
NetL1_1: L1.1 U5.2 | length 270.4
  Bottom Layer w10: L1.1 2106.54,2420 2240,2420 2255,2405 2255,2385 2244.53,2374.53 U5.2
NetL51_2: L51.2 R54.2 | length 100
  Bottom Layer w10: R54.2 L51.2
NetR5_2: R5.2 U1.94 | length 237.1
  Top Layer w10: U1.94 2501.89,3011.89 2515,3025 2625,3025 v2(2645,3045)
  Bottom Layer w10: v2(2645,3045) R5.2@2645,3098.46
NetR13_2: R13.2 U3.19 | length 166
  Bottom Layer w10: U3.19 2396.02,3051.02 2425,3080 2440,3080 2460,3100 R13.2
NetR14_1: R14.1 U2.4 | length 131.1
  Top Layer w10: v2(2060,3193.46) 2119.05,3134.41 U2.4
NetR15_2: R15.2 U2.3 U3.15 | length 232.6
  Top Layer w10: U2.3 2193.55,3160 2220,3133.55 v2(2220,3126.54)
  Bottom Layer w10: v2(2220,3126.54) 2220,3069.49 U3.15
NetR21_1: R21.1 U4.1 | length 204.6
  Bottom Layer w10: U4.1 2539.96,2309.53 R21.1
NetR22_2: R22.2 U4.16 | length 271.5
  Bottom Layer w10: U4.16 2486.33,2335.12 2615,2463.79 R22.2
NetR23_2: R23.2 U4.12 | length 407.4
  Top Layer w10: v1(2250,2345) 2295,2345 2310,2330 2320,2330 v1@2342.5,2307.5
  Bottom Layer w10: v1(2250,2345) 2270,2365 2270,2440 2346.54,2516.54 R23.2 ; v1@2343.47,2309.53 U4.12
  other v1: 2343,2310
NetR24_2: R24.2 U4.15 | length 272
  Bottom Layer w10: U4.15 2429.84,2344.84 2441.93,2356.93 2455.63,2356.93 2503.7,2405 2535,2405 2550,2420 2550,2481.54 R24.2
NetR42_2: R42.2 U1.95 U7.23 U8.4 | length 1293.4
  Top Layer w10: U1.95 2482.2,2957.8 2532.5,2907.5 2667.5,2907.5 v1(2695,2935) ; R42.2 v1(3120,2945) 3120,2905.64 3156.38,2869.26 U7.23 ; v1(3155,2815) 3156.5,2816.5 U7.23@3156.5,2857.09 ; v1(3225,2645) 3250,2620 3250,2565.08 U8.4
  Bottom Layer w10: v1(2695,2935) 2730,2970 3095,2970 v1(3120,2945) ; v1(3155,2815) 3220,2815 3290,2745 3290,2665 3270,2645 v1(3225,2645)
NetR43_2: R43.2 U1.96 U7.24 U8.3 | length 1166.8
  Top Layer w10: U1.96 2462.52,2952.48 2522.5,2892.5 2677.5,2892.5 v1(2720,2935) ; R43.2 3051.18,2946.54 U7.24 ; v1(3199,2645) 3199,2644.28 3235,2608.28 3235,2582.92 3212.8,2560.72 U8.3
  Bottom Layer w10: v1(2720,2935) 2730,2945 v1(3020,2945) ; v1(3140,2855) 3130,2845 3130,2765 3155,2740 3185,2740 3198.19,2726.81 v1@3198.19,2648.19
NetR51_1: R51.1 U9.6 | length 1134.2
  Top Layer w10: R51.1 v1(3140,2460) ; v1(3445,2440) 3445,2560 v1@3607.5,2722.5 ; v1(3610,2835) 3610,3000 3645,3035 3645,3075 U9.6@3616.69,3103.31
  Bottom Layer w10: v1(3140,2460) 3235,2460 3255,2440 v1(3445,2440) ; v1(3610,2725) v1(3610,2835)
NetR52_1: R52.1 U1.57 U9.4 | length 1676.5
  Top Layer w10: U1.57 2964.32,2561.89 2996.21,2530 v1(3140,2530) ; v1(3470,2530) 3640,2700 v1(3640,2725) ; v1(3640,2835) 3640,2985 3703.31,3048.31 U9.4
  Bottom Layer w10: v1(3140,2530) v1(3470,2530) ; R52.1 3440,3273.46 3440,3205 3500,3145 3675,3145 v1(3705,3115) ; v1(3640,2725) v1(3640,2835)
NetR53_2: R53.2 U10.6 | length 80.6
  Top Layer w10: U10.6 v1(3680.32,3319.68)
  Bottom Layer w10: v1(3680.32,3319.68) R53.2@3713.46,3286.54
NetR54_1: R54.1 U10.2 U10.3 | length 119.3
  Bottom Layer w10: v1(3710,3235) 3751.54,3235 R54.1
NetU1_25: U1.25 U3.5 | length 369
  Top Layer w10: U1.25 2358.78,2443.78 2480,2565 2480,2605 2525,2650 v1(2525,2700)
NetU1_26: U1.26 U3.1 | length 427.1
  Top Layer w10: U1.26 2383.78,2423.78 2630,2670 v1(2630,2700)
NetU1_51: U1.51 U7.11 | length 605.3
  Top Layer w10: U1.51 2940,2428.9 v1(2940,2385) ; v1(3095,2630) 3140,2675 3150,2675 3203.62,2728.62 U7.11
  Bottom Layer w10: v1(2940,2385) 3055,2385 3095,2425 v1(3095,2630)
NetU1_52: U1.52 U7.12 | length 682.3
  Top Layer w10: U1.52 2951.54,2463.46 2965,2450 v1(2965,2360) ; v1(3120,2615) 3219.37,2714.37 U7.12
  Bottom Layer w10: v1(2965,2360) 3065,2360 3120,2415 v1(3120,2615)
NetU1_55: U1.55 U9.3 | length 1333.5
  Top Layer w10: U1.55 2957.48,2522.52 2990,2490 v1(3140,2490) ; v1(3470,2465) 3470,2485 3670,2685 v1(3670,2725) ; v1(3670,2835) 3670,2970 3746.61,3046.61 U9.3
  Bottom Layer w10: v1(3140,2490) 3280,2490 3305,2465 v1(3470,2465) ; v1(3670,2725) v1(3670,2835)
NetU1_56: U1.56 U9.2 | length 1362.3
  Top Layer w10: U1.56 2962.8,2542.2 2995,2510 v1(3140,2510) ; v1(3505,2490) 3535,2490 3700,2655 v1(3700,2725) ; v1(3700,2835) 3700,2955 3789.92,3044.92 U9.2
  Bottom Layer w10: v1(3140,2510) 3485,2510 v1(3505,2490) ; v1(3700,2725) v1(3700,2835)
NetU1_68: U1.68
NetU1_69: U1.69
NetU2_2: U2.2 U3.16 | length 301.5
  Top Layer w10: U2.2 2219.41,3185.59 2245,3160 2245,3090 2270,3065 v2(2300,3065)
  Bottom Layer w10: v2(2300,3065) 2319.25,3045.75 U3.16
NetU9_13: U9.13 U10.5 | length 966.6
  Top Layer w10: U9.13 3616.69,2775.01 3570,2821.7 3570,2951.21 3425,3096.21 3425,3295 3485,3355 3680,3355 3699.68,3335.32 U10.5
OV_HSYNC: pad.D2 U1.29 | length 989
  Top Layer w10: v1(3025,2718) 3047,2718 3070,2695 3070,2628 v1(3030,2588)
  Bottom Layer w10: v1(2443,2375) 2443,2503 2490,2550 2645,2550 2670,2525 2850,2525 2913,2588 v1(3030,2588) ; pad.D2 2994.29,2718 v1(3025,2718)
OV_MCO1: U1.67
OV_PCLK: pad.E1 U1.31 | length 655.4
  Top Layer w10: U1.31 2482.2,2417.2 2775,2710 v1(2855,2710)
  Bottom Layer w10: v1(2855,2710) 2880,2710 2905.83,2735.83 pad.E1
OV_PWDN: pad.B1 U1.30 | length 641.4
  Top Layer w10: U1.30 v1@2462.52,2417.52 ; v1(2525,2430) 2757.61,2662.61 v1(2855,2662.61)
  Bottom Layer w10: v1(2465,2420) 2475,2430 v1(2525,2430) ; v1(2855,2662.61) pad.B1
OV_RESET: C5.1 CN5.1 CN5.2 pad.F2 R1.2 U1.14 | length 1496.4
  Top Layer w10: CN5.2 2208.58,2174.88 v1(2185,2198.46) 2208.58,2222.05 v1(2208.58,2436.85) ; v1(2314.88,2660.32) 2359.68,2660.32 2380,2640 2415,2640 2509.69,2734.69 v1(2855,2734.69)
  Bottom Layer w10: R1.2 v1(2210,2045) ; v1(2208.58,2436.85) 2230,2458.27 2230,2610 2280.32,2660.32 v1(2314.88,2660.32) ; v1(2855,2734.69) 2879.69,2734.69 2920.76,2775.76 2972.21,2775.76 pad.F2
OV_SIOC: pad.A3 U1.47 | length 417.1
  Top Layer w10: U1.47 v1@2797.17,2424.17 ; v1(3000,2550) 3012.13,2562.13 v1(3012.13,2638.2)
  Bottom Layer w10: v1@2800,2425 2835,2425 2870,2460 2870,2498.95 2921.05,2550 v1(3000,2550)
  other v1: 2798,2425
OV_SIOD: pad.A2 U1.48 | length 376.7
  Top Layer w10: U1.48 v1@2816.85,2444.85 ; v1(2980,2570) 2987.72,2577.72 v1(2987.72,2638.2)
  Bottom Layer w10: v1(2817,2445) 2830,2445 2855,2470 2855,2505.16 2919.84,2570 v1(2980,2570)
OV_VSYNC: pad.D1 U1.93 | length 601.6
  Top Layer w10: U1.93 2521.57,2948.43 v1(2544.79,2925.21)
  Bottom Layer w10: v1(2544.79,2925.21) 2544.79,2912.79 2767.57,2690 2885,2690 2906.43,2711.43 pad.D1
SD_CD: CN2.9 R117.2 U1.84 | length 1195.1
  Top Layer w10: U1.84 2698.74,3013.74 2735,3050 2800.25,3050 2813.95,3063.7 3058.7,3063.7 3070,3075 3425,3075 3520,2980 3520,2945 v1(3490,2915)
  Bottom Layer w10: v1(3490,2915) 3515,2915 3546.54,2946.54 R117.2
SD_CK: CN2.5 R116.2 U1.80 | length 1643.8
  Bottom Layer w10: v1(2777,3010) 2777,3032 2799.88,3054.88 3385.12,3054.88 3415,3025 3415,2770 CN2.5@3440.35,2744.65 ; CN2.5 3510.35,2744.65 3806.54,2448.46 R116.2
SD_CMD: CN2.3 R111.2 U1.83 | length 1845.3
  Top Layer w10: U1.83 2718.43,3012.21 2741.21,3035 2806.47,3035 2820.17,3048.7 3064.91,3048.7 3076.21,3060 3365,3060 3470,2955 3470,2803.28 3460,2793.28 3460,2730.36 3440,2710.36 3440,2684.65 v1(3466.61,2658.03)
  Bottom Layer w10: v1(3466.61,2658.03) 3541.97,2658.03 3760,2440 3760,2206.54 R111.2
SD_D0: CN2.7 R114.1 U1.65 | length 1610.6
  Top Layer w10: U1.65 2969.37,2719.37 2990,2740 3035,2740 3095,2800 v1(3095,2835) ; v1(3275,2885) 3395,2885 v1(3450,2830) ; v1(3485,2240) 3725,2480 v1(3725,2660)
  Bottom Layer w10: v1(3095,2835) 3145,2885 v1(3275,2885) ; CN2.7 3556.26,2831.26 3580,2855 3710,2855 3725,2840 v1(3725,2660)
SD_D1: CN2.8 R115.1 U1.66 | length 1041.2
  Top Layer w10: U1.66 2959.06,2739.06 3080,2860 v1(3080,2880) ; v1(3275,2920) 3295,2900 3425,2900 v1(3450,2875)
  Bottom Layer w10: v1(3080,2880) 3120,2920 v1(3275,2920) ; CN2.8 3619.57,2874.57 3746.54,3001.54 R115.1
SD_D2: CN2.1 R113.2 U1.78 | length 1527.5
  Bottom Layer w10: v1(2817,3010) 2831.88,3024.88 3358.91,3024.88 3380,3003.79 3380,2625 CN2.1@3440,2565 ; CN2.1 3605,2433.03 3605,2201.54 R113.2
SD_D3: CN2.2 R112.2 U1.79 | length 1535
  Bottom Layer w10: v1(2797,3010) 2797,3027 2809.88,3039.88 3365.12,3039.88 3395,3010 3395,2655 CN2.2@3440,2610 ; CN2.2 3525.28,2614.72 3646.54,2493.46 R112.2
SWCLK: CN1.2 U1.76 | length 1025.9
  Top Layer w10: v1(2480,2795) 2500,2815 v1(2735,2815) ; v1(2740,2920) 2830,2920 2856.22,2946.22 U1.76
  Bottom Layer w10: CN1.2 2044.92,2755.08 2220.08,2755.08 2280,2815 2415,2815 2435,2795 v1(2480,2795) ; v1(2735,2815) 2720,2830 2720,2903.33 2736.67,2920 v1(2740,2920)
SWDIO: CN1.4 R7.2 U1.72 | length 1259.8
  Top Layer w10: CN1.4 2044.92,2555.08 2225.08,2555.08 v1(2250,2580) ; v1(2402.5,2662.5) 2495,2755 2705,2755 v1(2765,2815) ; v1(2740,2900) 2785,2900 2827.83,2857.17 U1.72
  Bottom Layer w10: CN1.4 2040,2510 2070,2480 R7.2 ; v1(2250,2580) 2320,2580 v1(2402.5,2662.5) ; v1(2740,2900) 2740,2835 v1@2760,2815
pads on no net: CN2. CN22.3 CN22.6 U1.1 U1.2 U1.7 U1.8 U1.9 U1.15 U1.16 U1.17 U1.18 U1.23 U1.24 U1.32 U1.33 U1.34 U1.35 U1.36 U1.38 U1.39 U1.41 U1.43 U1.44 U1.45 U1.46 U1.53 U1.54 U1.58 U1.70 U1.71 U1.77 U1.81 U1.82 U1.85 U1.86 U1.87 U1.88 U1.89 U1.90 U1.91 U2. U3.2 U3.3 U3.6 U3.8 U3.9 U3.10 U3.11 U3.12 U3.13 U3.14 U3.22 U3.23 U3.24 U3.27 U3.28 U5.6 U5.7 U7.1 U7.2 U7.3 U7.4 U7.5 U7.6 U7.7 U7.14 U7.15 U7.16 U7.17 U7.19 U7.21 U9.5 U9.15 U9.16 U9.17 U9.18

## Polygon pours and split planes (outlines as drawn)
GND on GROUND (split plane): 3916.91,1988.6 1988.6,1988.6 1988.6,3365.73 3916.91,3365.73
3.3V on VCC (split plane): 3916.91,1988.6 1988.6,1988.6 1988.6,3365.73 2104.91,3365.73 2104.91,3200 2105.26,3197.39 2106.26,3194.96 2107.87,3192.87 2259.91,3040.82 2259.91,2955 2259.91,2350 2260.26,2347.39 2261.26,2344.96 2262.87,2342.87 2302.87,2302.87 2304.96,2301.26 2306.68,2300.55 2307.39,2300.26 2310,2299.91 2390,2299.91 2392.61,2300.26 2395.04,2301.26 2397.13,2302.87 2447.13,2352.87 2448.74,2354.96 2449.24,2356.17 2449.74,2357.39 2450.09,2360 2450.09,2845.82 2602.13,2997.87 2603.74,2999.96 2604.74,3002.39 2605.09,3005 2605.09,3154.91 2925,3154.91 2927.61,3155.26 2930.04,3156.26 2932.13,3157.87 2954.18,3179.91 3070.82,3179.91 3099.91,3150.82 3099.91,3120 3100.26,3117.39 3101.26,3114.96 3102.87,3112.87 3142.87,3072.87 3144.96,3071.26 3146.68,3070.55 3147.39,3070.26 3150,3069.91 3349.91,3069.91 3349.91,2390.09 2550,2390.09 2547.39,2389.74 2546.17,2389.24 2544.96,2388.74 2542.87,2387.13 2462.87,2307.13 2461.26,2305.04 2460.26,2302.61 2459.91,2300 2459.91,2250 2460.26,2247.39 2461.26,2244.96 2462.87,2242.87 2464.96,2241.26 2467.39,2240.26 2470,2239.91 2615,2239.91 2617.61,2240.26 2620.04,2241.26 2622.13,2242.87 2623.74,2244.96 2624.74,2247.39 2625.09,2250 2625.09,2324.91 3119.91,2324.91 3119.91,2050 3120.26,2047.39 3121.26,2044.96 3122.87,2042.87 3124.96,2041.27 3127.39,2040.26 3130,2039.91 3415,2039.91 3417.61,2040.26 3420.04,2041.27 3422.13,2042.87 3423.74,2044.96 3424.74,2047.39 3425.09,2050 3425.09,3270 3424.74,3272.61 3423.74,3275.04 3422.13,3277.13 3420.04,3278.74 3417.61,3279.74 3415,3280.09 2485.09,3280.09 2485.09,3365.73 3916.91,3365.73
5V_USB on VCC (split plane): 2464.91,3270 2464.91,3165 2465.26,3162.39 2466.26,3159.96 2467.87,3157.87 2469.96,3156.26 2472.39,3155.26 2475,3154.91 2584.91,3154.91 2584.91,3009.18 2432.87,2857.13 2431.26,2855.04 2430.26,2852.61 2429.91,2850 2429.91,2364.18 2385.82,2320.09 2314.18,2320.09 2280.09,2354.18 2280.09,2955 2280.09,3045 2279.74,3047.61 2278.74,3050.04 2277.13,3052.13 2125.09,3204.18 2125.09,3365.73 2464.91,3365.73
3.7V_LI on VCC (split plane): 3404.91,2060.09 3140.09,2060.09 3140.09,2335 3139.74,2337.61 3138.74,2340.04 3137.13,2342.13 3135.04,2343.74 3132.61,2344.74 3130,2345.09 2620,2345.09 2617.39,2344.74 2614.96,2343.74 2612.87,2342.13 2607.87,2337.13 2606.26,2335.04 2605.26,2332.61 2604.91,2330 2604.91,2260.09 2480.09,2260.09 2480.09,2295.82 2554.18,2369.91 3360,2369.91 3362.61,2370.26 3365.04,2371.26 3367.13,2372.87 3368.74,2374.96 3369.74,2377.39 3370.09,2380 3370.09,3080 3369.74,3082.61 3368.74,3085.04 3367.13,3087.13 3365.04,3088.74 3362.61,3089.74 3360,3090.09 3154.18,3090.09 3120.09,3124.18 3120.09,3155 3119.74,3157.61 3118.74,3160.04 3117.13,3162.13 3082.13,3197.13 3080.04,3198.74 3077.61,3199.74 3075,3200.09 2950,3200.09 2947.39,3199.74 2946.68,3199.45 2944.96,3198.74 2942.87,3197.13 2920.82,3175.09 2485.09,3175.09 2485.09,3259.91 3404.91,3259.91

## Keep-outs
Keep-Out Layer:
  the board outline again, w20

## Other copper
VCC (plane layer: these items are gaps in the copper):
  lines w20: 2115,3385.83 2115,3200 2270,3045 2270,2955 2270,2350 2310,2310 2390,2310 2440,2360 2440,2850 2595,3005 2595,3165 ; 2475,3385.83 2475,3270 ; 2475,3270 3415,3270 3415,2050 3130,2050 3130,2335 2620,2335 2615,2330 2615,2250 2470,2250 2470,2300 2550,2380 3360,2380 3360,3080 3150,3080 3110,3120 3110,3155 3075,3190 2950,3190 2925,3165 2475,3165 2475,3270

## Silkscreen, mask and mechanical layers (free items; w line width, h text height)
Top Overlay:
  circle w7.87: c2342.52,2086.61 r78.74
  circle w7.87: c3523.62,2086.61 r78.74
  circle w7.87: c3523.62,3267.72 r78.74
  circle w7.87: c2342.52,3267.72 r78.74
  lines w10: 3425.2,2224.41 3425.2,2696.85 3897.64,2696.85 3897.64,2224.41 3425.2,2224.41
Bottom Overlay:
  circle w9.84: c2923.39,2603.2 r4.92
  lines w4: 3006.32,2699.22 3017.32,2699.22 ; 3012.13,2692.88 3012.13,2704.88
  lines w7.87: 2937.32,2634.14 2955.91,2615.56 ; 2937.32,2615.56 2937.32,2782.88 3086.93,2782.88 3086.93,2615.56 2937.32,2615.56
  lines w8: 2705,2325.67 3334.96,2325.67 3334.96,3034.33 2705.04,3034.33 2705.04,2325.67 ; 2740,2372.91 2740,2987.09 ; 2740.47,2372.91 3299.53,2372.91 ; 2740.47,2987.09 3300,2987.09 ; 2940,2325.67 2940,2245 ccw(c3018.73,2246.38) 3097.46,2245.63 3097.46,2323.2 ; 2940,3034.33 2940,3115 cw(c3018.73,3113.49) 3097.46,3112.18 3097.45,3036.79 ; 3299.53,2373.39 3299.53,2986.61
